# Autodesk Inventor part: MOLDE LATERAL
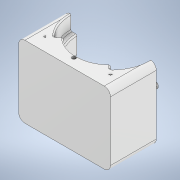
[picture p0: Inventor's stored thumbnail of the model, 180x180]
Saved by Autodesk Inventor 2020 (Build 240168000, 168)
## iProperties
Created: 2022-09
Part Number: MOLDE LATERAL
Material: PVC, no plastificado
Document SubType Name: Modeling
Designer: SEBAS
Density: 1.29 g/cm^3
Appearance: Suave - Blanco
Author: SEBAS
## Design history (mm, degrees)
sketch "Boceto3"
  geometry: L1 (37, 58)-(37, 0); L2 (37, 0)-(27, 0); L3 (27, 0)-(27, 5); L4 (27, 5)-(32, 5); L5 (32, 5)-(32, 12); L6 (32, 12)-(27, 12); L7 (27, 12)-(27, 27); L8 (27, 27)-(32, 27); L9 (32, 27)-(32, 31); L10 (32, 31)-(27, 31); L11 (27, 31)-(27, 46); L12 (27, 46)-(32, 46); L13 (32, 46)-(32, 53); L14 (32, 53)-(27, 53); L15 (27, 53)-(27, 58); L16 (27, 58)-(37, 58); L17 (0, 0)-(0, 55); L18 (27, 5)-(27, 12); L19 (27, 27)-(27, 31); L20 (27, 53)-(27, 46); L21 (32, 53)-(32, 58); L22 (32, 5)-(32, 0)
  constraints: 44 end point, 10 perpendicular, 8 point on line, 5 collinear, 3 vertical, 2 horizontal alignment, 2 midpoint, 1 horizontal, 1 vertical alignment
  dimensions: "d27" = 32 distance from line of L17.start L5; "d28" = 10 distance of L1.end L2.end; "d29" = 5 distance of L4.end L3.end; "d30" = 5 distance of L14.end L15.end; "d33" = 4 distance of L8.end L9.end; "d34" = 15 distance of L10.end L11.end; "d35" = 7 distance of L4.end L5.end
sketch "Boceto4"
  geometry: L1 (0, -13.5)-(0, 13.5); L2 (37, 37)-(-37, 37); L3 (-37, 37)-(-37, -37); L4 (-37, -37)-(37, -37); L5 (37, -37)-(37, 37); L6 (37, 37)-(-37, -37); L7 (-37, 37)-(37, -37); L8 (-27, 27)-(27, 27); L9 (27, 27)-(27, -27); L10 (27, -27)-(-27, -27); L11 (-27, -27)-(-27, 27); L12 (-27, 27)-(27, -27); L13 (27, 27)-(-27, -27); L14 (37, 0)-(-37, 0); 4 further points
  constraints: 28 end point, 7 midpoint, 4 parallel, 4 perpendicular, 2 horizontal, 1 coincident
  dimensions: "d38" = 37 horizontal distance of L2.end point (0, 0); "d39" = 10 distance between parallel lines of L2 L8
revolve "Revolución2" stored, may be unused: angle "d40" = 180 deg
extrude "Extrusión2" join sketch "Boceto4" stored distance "d41" = 10; taper "d42" = 0 deg
revolve "Revolución3" stored, may be unused: angle "d43" = 90 deg
fillet "Empalme2" dims "d44" = 5
sketch "Boceto5"
  geometry: L1 (5, 5)-(0, 5) reference; L2 (0, 5)-(0, 0) reference; L3 (0, 0)-(5, 0) reference; L4 (5, 0)-(5, -7) reference; L5 (5, -7)-(0, -7) reference; L6 (0, -7)-(0, -22) reference; L7 (0, -22)-(5, -22) reference; L8 (5, -22)-(5, -26) reference; L9 (5, -26)-(0, -26) reference; L10 (0, -26)-(0, -41) reference; L11 (0, -41)-(5, -41) reference; L12 (5, -41)-(5, -48) reference; L13 (5, -48)-(0, -48) reference; L14 (0, -48)-(0, -53) reference; L15 (0, -53)-(5, -53) reference; L16 (10, -48)-(10, 0) reference; L17 (-64, -48)-(-64, 0) reference; L18 (-54, -53)-(-59, -53) reference; L19 (-54, -48)-(-54, -53) reference; L20 (-54, -48)-(-59, -48) reference; L21 (-59, -48)-(-59, -41) reference; L22 (-59, -41)-(-54, -41) reference; L23 (-54, -26)-(-54, -41) reference; L24 (-54, -26)-(-59, -26) reference; L25 (-59, -26)-(-59, -22) reference; L26 (-59, -22)-(-54, -22) reference; L27 (-54, -7)-(-54, -22) reference; L28 (-54, -7)-(-59, -7) reference; L29 (-59, -7)-(-59, 0) reference; L30 (-59, 0)-(-54, 0) reference; L31 (-54, 5)-(-54, 0) reference; L32 (-59, 5)-(-54, 5) reference; L33 (0, -26)-(0, -41) reference; L34 (0, -33.5)-(10, -33.5); L35 (0, -7)-(0, -22) reference; L36 (0, -14.5)-(10, -14.5); L37 (-54, -33.5)-(-64, -33.5); L38 (-54, -7)-(-54, -22) reference; L39 (-54, -14.5)-(-64, -14.5); L40 (-64, -48)-(-64, 0) reference; L41 (7.5, -31)-(2.5, -31); L42 (2.5, -31)-(2.5, -36); L43 (2.5, -36)-(7.5, -36); L44 (7.5, -36)-(7.5, -31); L45 (7.5, -31)-(2.5, -36); L46 (2.5, -31)-(7.5, -36); L47 (-56, -30.5)-(-62, -30.5); L48 (-62, -30.5)-(-62, -36.5); L49 (-62, -36.5)-(-56, -36.5); L50 (-56, -36.5)-(-56, -30.5); L51 (-56, -30.5)-(-62, -36.5); L52 (-62, -30.5)-(-56, -36.5); L53 (-56.5, -12)-(-61.5, -12); L54 (-61.5, -12)-(-61.5, -17); L55 (-61.5, -17)-(-56.5, -17); L56 (-56.5, -17)-(-56.5, -12); L57 (-56.5, -12)-(-61.5, -17); L58 (-61.5, -12)-(-56.5, -17); L59 (8, -11.5)-(2, -11.5); L60 (2, -11.5)-(2, -17.5); L61 (2, -17.5)-(8, -17.5); L62 (8, -17.5)-(8, -11.5); L63 (8, -11.5)-(2, -17.5); L64 (2, -11.5)-(8, -17.5); A1 r 5 centre (5, 0) between (10, 0) and (5, 5) reference; A2 r 5 centre (5, -48) between (5, -53) and (10, -48) reference; A3 r 5 centre (-59, 0) between (-59, 5) and (-64, 0) reference; A4 r 5 centre (-59, -48) between (-64, -48) and (-59, -53) reference; 5 further points; 1 other entity
  constraints: 56 end point, 15 midpoint, 8 parallel, 7 point on line, 6 equal length, 6 perpendicular, 4 horizontal, 2 other
  dimensions: "d45" = 5 distance of L42.end L43.end; "d51" = 6 distance of L48.end L49.end
  node "Contorno proyectado1"
  node "Contorno proyectado2"
extrude "Extrusión3" join sketch "Boceto5" distance "d46" = 4; taper "d47" = 0 deg
extrude "Extrusión4" cut sketch "Boceto5" distance "d48" = 5; taper "d49" = 0 deg
fillet "Empalme3" dims "d50" = 2
sketch "Boceto6"
  geometry: L1 (32, 31)-(-32, 31) reference; L2 (32, 27)-(32, 31) reference; L3 (32, 27)-(-32, 27) reference; L4 (-32, 31)-(-32, 27) reference; L5 (32, 29)-(-32, 29); L6 (-32, 31)-(-32, 27) reference; L7 (12.5, 16.5)-(-12.5, 16.5); L8 (-12.5, 16.5)-(-12.5, 41.5); L9 (-12.5, 41.5)-(12.5, 41.5); L10 (12.5, 41.5)-(12.5, 16.5); L11 (12.5, 16.5)-(-12.5, 41.5); L12 (-12.5, 16.5)-(12.5, 41.5); 2 further points
  constraints: 14 end point, 5 midpoint, 2 parallel, 2 perpendicular, 1 horizontal
  dimensions: "d53" = 25 distance of L8.end L9.end
extrude "Extrusión5" cut sketch "Boceto6" distance "d54" = 33; taper "d55" = 0 deg
fillet "Empalme5" dims "d56" = 2
revolve "Revolución4" stored, may be unused: angle "d58" = 225 deg; dims "d59" = 45 deg
fillet "Empalme7" dims "d60" = 1
fillet "Empalme8" dims "d61" = 1
sketch "Boceto7"
  geometry: L1 (53.202, -14.384)-(51.079, -16.507) reference; L2 (12.921, -16.507)-(10.798, -14.384) reference; C1 r 1.5 at (32, -7.5); A1 r 28 centre (32, -37) between (51.079, -16.507) and (12.921, -16.507) reference; A2 r 31 centre (32, -37) between (53.92, -15.08) and (10.08, -15.08) reference; A3 r 29.5 centre (32, -37) between (52.141, -15.445) and (11.859, -15.445); 3 further points
  constraints: 3 point on circle, 2 centre point, 2 midpoint
  dimensions: "d62" = 3 diameter of C1
extrude "Extrusión6" cut sketch "Boceto7" stored distance "d63" = 10; taper "d64" = 0 deg
node "Sólido2"
node "Contorno proyectado3"
